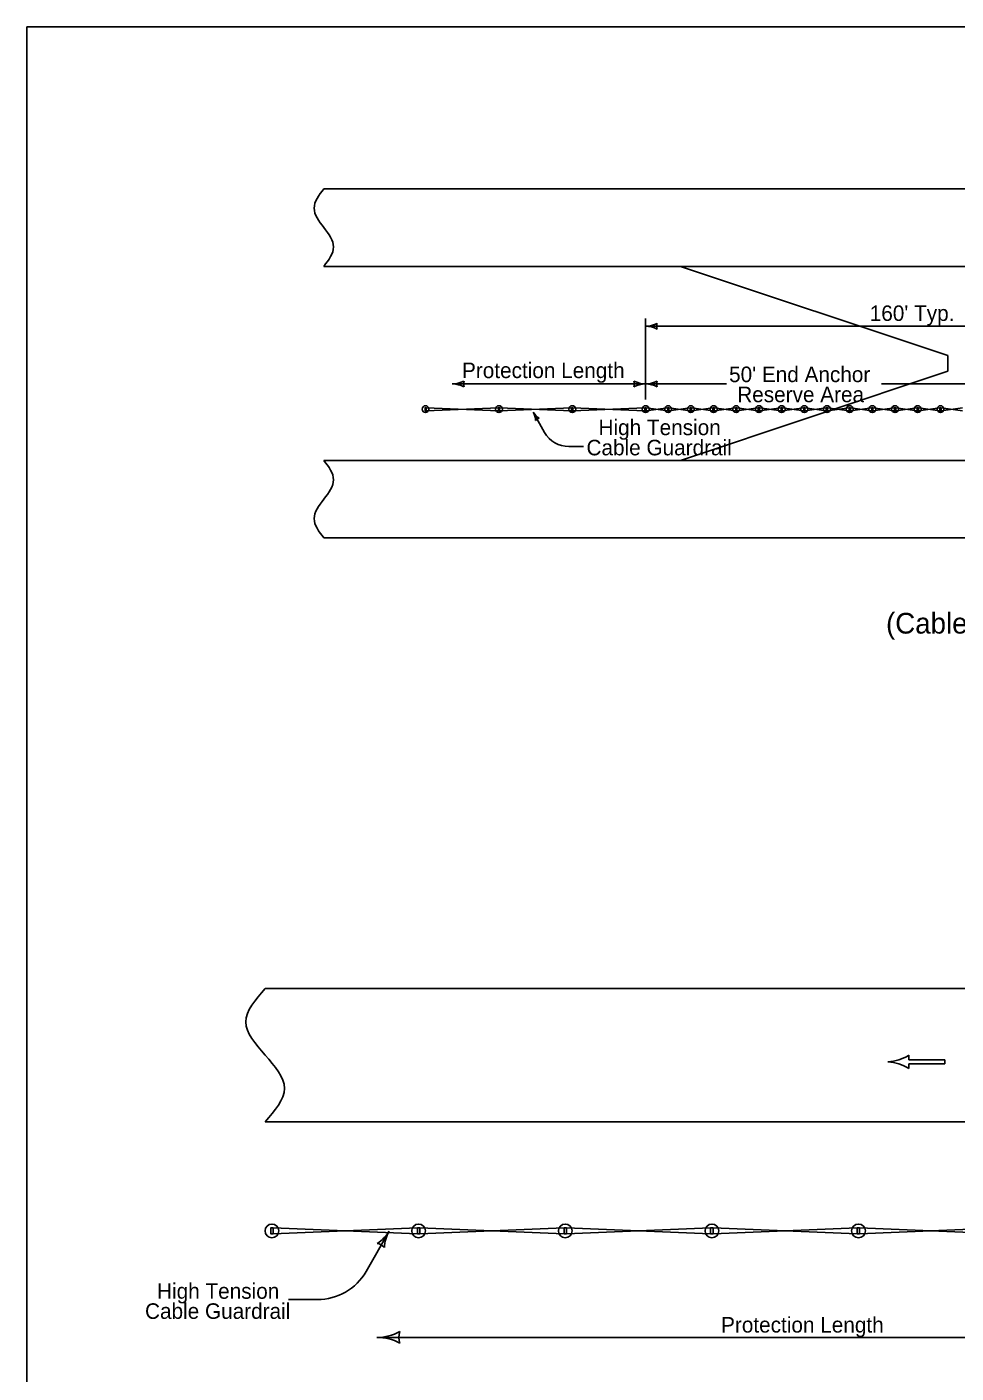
# Model space of a CAD drawing. Extents: x 10133 to 81668, y 7924 to 11018.
# Drawn here: x 13733 to 14451, y 8903 to 9944 of the extents above; entities that cross this region are included whole.
import ezdxf

# ---------------------------------------------------------------- set-up
doc = ezdxf.new("R2010")
doc.units = 0
for name, color, linetype in [('dsnCellElements', 7, 'Continuous'), ('DsnShtRevisedText', 7, 'Continuous'), ('dsnStdDimension', 7, 'Continuous'), ('Level 8', 7, 'Continuous'), ('SheetBorder', 7, 'Continuous')]:
    doc.layers.add(name, color=color, linetype=linetype)

msp = doc.modelspace()

# ---------------------------------------------------------------- linework, layer by layer
at = {"layer": 'dsnCellElements'}
for p, q in [((14097.2, 9649.6), (14041.4, 9647.3)), ((14097.2, 9647.3), (14041.4, 9649.6)), ((14153.9, 9649.6), (14098.1, 9647.3)), ((14153.9, 9647.3), (14098.1, 9649.6)), ((14210.6, 9649.6), (14154.8, 9647.3)), ((14210.6, 9647.3), (14154.8, 9649.6)), ((14228.2, 9649.6), (14211.5, 9647.3)), ((14228.2, 9647.3), (14211.5, 9649.6)), ((14245.7, 9649.6), (14229.1, 9647.3)), ((14245.7, 9647.3), (14229.1, 9649.6)), ((14263.2, 9649.6), (14246.6, 9647.3)), ((14263.2, 9647.3), (14246.6, 9649.6)), ((14280.8, 9649.6), (14264.2, 9647.3)), ((14280.8, 9647.3), (14264.2, 9649.6)), ((14298.3, 9649.6), (14281.7, 9647.3)), ((14298.3, 9647.3), (14281.7, 9649.6)), ((14315.9, 9649.6), (14299.3, 9647.3)), ((14315.9, 9647.3), (14299.3, 9649.6)), ((14333.4, 9649.6), (14316.8, 9647.3)), ((14333.4, 9647.3), (14316.8, 9649.6)), ((14350.9, 9647.3), (14334.4, 9649.6)), ((14350.9, 9649.6), (14334.4, 9647.3)), ((14368.5, 9649.6), (14351.9, 9647.3)), ((14368.5, 9647.3), (14351.9, 9649.6)), ((14386, 9649.6), (14369.5, 9647.3)), ((14386, 9647.3), (14369.5, 9649.6)), ((14403.6, 9649.6), (14387, 9647.3)), ((14403.6, 9647.3), (14387, 9649.6)), ((14421.1, 9649.6), (14404.6, 9647.3)), ((14421.1, 9647.3), (14404.6, 9649.6)), ((14438.7, 9649.6), (14422.1, 9647.3)), ((14438.7, 9647.3), (14422.1, 9649.6)), ((14456.2, 9649.6), (14439.7, 9647.3)), ((14456.2, 9647.3), (14439.7, 9649.6)), ((14034.6, 9015.5), (13923.1, 9011)), ((14034.6, 9011), (13923.1, 9015.5)), ((14148, 9015.5), (14036.5, 9011)), ((14148, 9011), (14036.5, 9015.5)), ((14261.4, 9015.5), (14149.9, 9011)), ((14261.4, 9011), (14149.9, 9015.5)), ((14374.8, 9015.5), (14263.3, 9011)), ((14374.8, 9011), (14263.3, 9015.5)), ((14488.2, 9015.5), (14376.7, 9011)), ((14488.2, 9011), (14376.7, 9015.5))]:
    msp.add_line(p, q, dxfattribs=at)
for points in [[(14041.4, 9647.3), (14041.4, 9649.6), (14040.5, 9649.6), (14040.5, 9647.3)], [(14098.1, 9647.3), (14098.1, 9649.6), (14097.2, 9649.6), (14097.2, 9647.3)], [(14098.1, 9647.3), (14098.1, 9649.6), (14097.2, 9649.6), (14097.2, 9647.3)], [(14154.8, 9647.3), (14154.8, 9649.6), (14153.9, 9649.6), (14153.9, 9647.3)], [(14154.8, 9647.3), (14154.8, 9649.6), (14153.9, 9649.6), (14153.9, 9647.3)], [(14211.5, 9647.3), (14211.5, 9649.6), (14210.6, 9649.6), (14210.6, 9647.3)], [(14211.5, 9647.3), (14211.5, 9649.6), (14210.6, 9649.6), (14210.6, 9647.3)], [(14229.1, 9647.3), (14229.1, 9649.6), (14228.2, 9649.6), (14228.2, 9647.3)], [(14246.6, 9647.3), (14246.6, 9649.6), (14245.7, 9649.6), (14245.7, 9647.3)], [(14264.2, 9647.3), (14264.2, 9649.6), (14263.2, 9649.6), (14263.2, 9647.3)], [(14281.7, 9647.3), (14281.7, 9649.6), (14280.8, 9649.6), (14280.8, 9647.3)], [(14299.3, 9647.3), (14299.3, 9649.6), (14298.3, 9649.6), (14298.3, 9647.3)], [(14316.8, 9647.3), (14316.8, 9649.6), (14315.9, 9649.6), (14315.9, 9647.3)], [(14334.4, 9647.3), (14334.4, 9649.6), (14333.4, 9649.6), (14333.4, 9647.3)], [(14351.9, 9647.3), (14351.9, 9649.6), (14350.9, 9649.6), (14350.9, 9647.3)], [(14369.5, 9647.3), (14369.5, 9649.6), (14368.5, 9649.6), (14368.5, 9647.3)], [(14387, 9647.3), (14387, 9649.6), (14386, 9649.6), (14386, 9647.3)], [(14404.6, 9647.3), (14404.6, 9649.6), (14403.6, 9649.6), (14403.6, 9647.3)], [(14422.1, 9647.3), (14422.1, 9649.6), (14421.1, 9649.6), (14421.1, 9647.3)], [(14439.7, 9647.3), (14439.7, 9649.6), (14438.7, 9649.6), (14438.7, 9647.3)], [(13923.1, 9011), (13923.1, 9015.5), (13921.2, 9015.5), (13921.2, 9011)], [(14036.5, 9011), (14036.5, 9015.5), (14034.6, 9015.5), (14034.6, 9011)], [(14036.5, 9011), (14036.5, 9015.5), (14034.6, 9015.5), (14034.6, 9011)], [(14149.9, 9011), (14149.9, 9015.5), (14148, 9015.5), (14148, 9011)], [(14149.9, 9011), (14149.9, 9015.5), (14148, 9015.5), (14148, 9011)], [(14263.3, 9011), (14263.3, 9015.5), (14261.4, 9015.5), (14261.4, 9011)], [(14263.3, 9011), (14263.3, 9015.5), (14261.4, 9015.5), (14261.4, 9011)], [(14376.7, 9011), (14376.7, 9015.5), (14374.8, 9015.5), (14374.8, 9011)], [(14376.7, 9011), (14376.7, 9015.5), (14374.8, 9015.5), (14374.8, 9011)]]:
    msp.add_lwpolyline(points, close=True, dxfattribs=at)
for centre, radius in [((14040.9, 9648.5), 2.66), ((14097.7, 9648.5), 2.66), ((14097.7, 9648.5), 2.66), ((14154.4, 9648.5), 2.66), ((14154.4, 9648.5), 2.66), ((14211.1, 9648.5), 2.66), ((14211.1, 9648.5), 2.66), ((14228.6, 9648.5), 2.66), ((14246.1, 9648.5), 2.66), ((14263.7, 9648.5), 2.66), ((14281.2, 9648.5), 2.66), ((14298.8, 9648.5), 2.66), ((14316.3, 9648.5), 2.66), ((14333.9, 9648.5), 2.66), ((14351.4, 9648.5), 2.66), ((14369, 9648.5), 2.66), ((14386.5, 9648.5), 2.66), ((14404.1, 9648.5), 2.66), ((14421.6, 9648.5), 2.66), ((14439.2, 9648.5), 2.66), ((13922.1, 9013.2), 5.32), ((14035.5, 9013.2), 5.32), ((14035.5, 9013.2), 5.32), ((14149, 9013.2), 5.32), ((14149, 9013.2), 5.32), ((14262.4, 9013.2), 5.32), ((14262.4, 9013.2), 5.32), ((14375.8, 9013.2), 5.32), ((14375.8, 9013.2), 5.32)]:
    msp.add_circle(centre, radius, dxfattribs=at)
at = {"layer": 'DsnShtRevisedText'}
for p, q in [((14211.1, 9656), (14211.1, 9718.6)), ((14534, 9712.6), (14211.1, 9712.6)), ((14188.4, 9668), (14061.6, 9668)), ((14211.1, 9668), (14188.4, 9668)), ((14273.7, 9668), (14211.1, 9668)), ((14478.4, 9668), (14393.7, 9668)), ((14133, 9630.5), (14124.1, 9646.1)), ((14151.8, 9619.7), (14163.1, 9619.7)), ((14414.7, 9149), (14414.7, 9145.4)), ((14398.5, 9143.9), (14398.5, 9143.9)), ((14414.7, 9145.4), (14442.7, 9145.4)), ((14442.7, 9142.4), (14414.7, 9142.4)), ((14414.7, 9142.4), (14414.7, 9138.8)), ((14442.7, 9145.4), (14442.7, 9142.4)), ((13994.9, 8981.7), (14012.7, 9013)), ((13957.3, 8960.1), (13934.8, 8960.1)), ((14391.7, 8930.8), (14003.1, 8930.8)), ((14559.7, 8930.8), (14391.7, 8930.8))]:
    msp.add_line(p, q, dxfattribs=at)
for centre, radius, start, end in [((14211.1, 9731.7), 19.1, 270, 298.0725), ((14211.1, 9693.5), 19.1, 61.9275, 90), ((14227.1, 9712.6), 7.39, 162.2666, 197.7334), ((14061.6, 9687.1), 19.1, 270, 298.0725), ((14077.7, 9668), 7.39, 162.2666, 197.7334), ((14195, 9668), 7.39, 342.2666, 17.7333), ((14211.1, 9687.1), 19.1, 241.9275, 270), ((14211.1, 9687.1), 19.1, 270, 298.0725), ((14227.1, 9668), 7.39, 162.2666, 197.7334), ((14061.6, 9648.9), 19.1, 61.9275, 90), ((14211.1, 9648.9), 19.1, 90, 118.0725), ((14211.1, 9648.9), 19.1, 61.9275, 90), ((14112.4, 9639.3), 13.6, 2.1589, 30.2314), ((14135.9, 9653), 13.6, 210.2314, 238.3038), ((14129.9, 9636.3), 5.25, 102.498, 137.9647), ((14151.8, 9641.4), 21.8, 210.2243, 270), ((14397.2, 9176.6), 32.7, 272.352, 302.382), ((14397.2, 9111.2), 32.7, 57.618, 87.648), ((13989.2, 9026.7), 27.2, 301.6962, 329.7686), ((14036.2, 8999.3), 27.2, 149.7686, 177.8411), ((14001.2, 8993.3), 10.5, 42.0353, 77.502), ((13957.3, 9003.6), 43.5, 270, 329.7757), ((14003.1, 8969.1), 38.3, 270, 298.0725), ((14003.1, 8892.6), 38.3, 61.9275, 90), ((14035.1, 8930.8), 14.8, 162.2666, 197.7334)]:
    msp.add_arc(centre, radius, start, end, dxfattribs=at)
at = {"layer": 'dsnStdDimension'}
for p, q in [((13962.2, 9818.9), (15077.9, 9818.9)), ((13962.2, 9758.9), (14238, 9758.9)), ((14445, 9689.9), (14238, 9758.9)), ((14802, 9758.9), (14238, 9758.9)), ((14445, 9689.9), (14445, 9677.9)), ((14445, 9677.9), (14238, 9608.9)), ((13962.2, 9608.9), (14241.1, 9608.9)), ((14241.1, 9608.9), (14802, 9608.9)), ((13962.2, 9548.9), (15077.9, 9548.9)), ((15137.3, 9200.5), (13916.8, 9200.5)), ((15137.3, 9097.6), (13916.8, 9097.6))]:
    msp.add_line(p, q, dxfattribs=at)
for points in [[(13962.2, 9758.9), (13969.7, 9773.9), (13962.2, 9788.9), (13954.7, 9803.9), (13962.2, 9818.9)], [(13962.2, 9608.9), (13969.7, 9593.9), (13962.2, 9578.9), (13954.7, 9563.9), (13962.2, 9548.9)], [(13916.8, 9200.5), (13901.8, 9174.8), (13916.8, 9149.1), (13931.8, 9123.3), (13916.8, 9097.6)]]:
    msp.add_spline(points, degree=3, dxfattribs=at)
at = {"layer": 'SheetBorder'}
msp.add_lwpolyline([(13732.5, 9944), (16867.5, 9944), (16867.5, 7924), (13732.5, 7924)], close=True, dxfattribs=at)

# ---------------------------------------------------------------- texts
at = {"layer": 'DsnShtRevisedText'}
for s, p in [("160' Typ.", (14384.5, 9716.7)), ('Protection Length', (14069.1, 9672.5)), ("50' End Anchor", (14275.7, 9669.4)), ('Reserve Area', (14282, 9653.9)), ('High Tension', (14174.7, 9628.4)), ('Cable Guardrail', (14165.4, 9612.8)), ('High Tension', (13833.2, 8960.7)), ('Cable Guardrail', (13823.9, 8945.2)), ('Protection Length', (14269.5, 8934.6))]:
    msp.add_text(s, height=12, dxfattribs=at).set_placement(p)
at = {"layer": 'Level 8'}
msp.add_text('(Cable stays on same side)', height=16, dxfattribs=at).set_placement((14397.1, 9475))

doc.saveas('drawing.dxf')
